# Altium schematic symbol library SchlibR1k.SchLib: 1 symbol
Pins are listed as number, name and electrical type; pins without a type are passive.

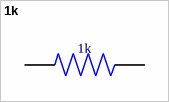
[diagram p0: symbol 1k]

## 1k
designator 1k  (value not drawn)
Res Thick Film 3.2 x 1.6 mm 6.8K Ohm 1% 0.25W(1/4W) 100ppm/ C Molded SMD Paper T/R; MP: RC1206FR-076K8L
footprint 1k
pins: 1, 2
